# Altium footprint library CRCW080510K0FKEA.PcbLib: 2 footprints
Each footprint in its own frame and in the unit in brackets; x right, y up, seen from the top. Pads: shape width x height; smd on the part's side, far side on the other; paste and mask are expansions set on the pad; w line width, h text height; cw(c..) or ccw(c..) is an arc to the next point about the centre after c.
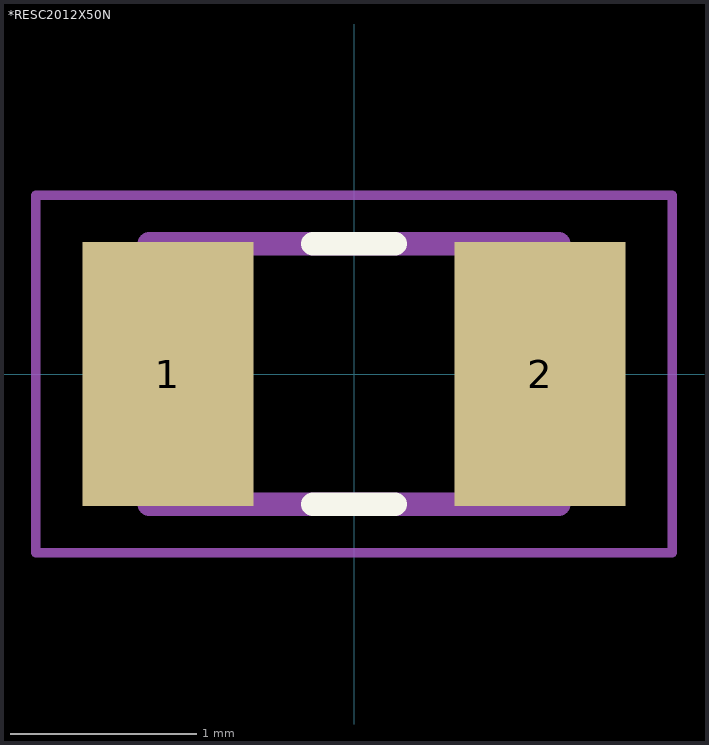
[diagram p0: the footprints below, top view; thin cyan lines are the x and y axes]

## *RESC2012X50N [mm]
pads (2):
  rect 0.92x1.42 smd: 1(-1,0) 2(1,0)
Top Overlay:
  lines w0.127: -0.22,-0.7 0.22,-0.7 ; -0.22,0.7 0.22,0.7
Mechanical 13:
  lines w0.127: -1.1,-0.7 -1.1,0.7 ; -1.1,-0.7 1.1,-0.7 ; -1.1,-0.7 -1.1,0.7 ; -1.1,-0.7 1.1,-0.7 ; -1.1,0.7 1.1,0.7 ; -1.1,0.7 1.1,0.7 ; 1.1,-0.7 1.1,0.7 ; 1.1,-0.7 1.1,0.7
Mechanical 15:
  lines w0.05: -1.71,-0.96 -1.71,0.96 1.71,0.96 1.71,-0.96 -1.71,-0.96

## PCBComponent_1 [mm]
